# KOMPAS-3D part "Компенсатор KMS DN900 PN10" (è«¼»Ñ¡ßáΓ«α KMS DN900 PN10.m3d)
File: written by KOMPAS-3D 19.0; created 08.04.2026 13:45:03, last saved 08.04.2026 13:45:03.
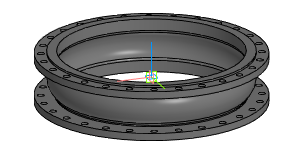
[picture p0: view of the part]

Document properties: Автор: Энергия; Полное имя файла: Z:\3.Личные\kachalov\3d для проектировщиков\7.1 Компенсатор\stp_Компенсатор KSM\Компенсатор KMS DN900 PN10.m3d

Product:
- Part/product: Компенсатор KMS DN900 PN10

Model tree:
1. Операция без истории:1  (labels: Компенсатор KMS DN900 PN10)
